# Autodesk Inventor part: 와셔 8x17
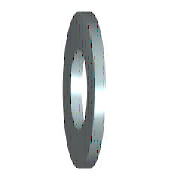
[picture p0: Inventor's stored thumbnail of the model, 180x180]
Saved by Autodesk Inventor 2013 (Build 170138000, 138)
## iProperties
IsCustomPart: 1
Created: 2012-02
Part Number: 와셔 8x17
Material: 강철, 연강
Description: 평면 와셔
Document SubType Name: Modeling
Standard: KS B 1326
Designer: mduedu
Standards Organization: KS
Language: ko-KR
Size Designation: 8x17
Categories: <MemberInstance><Categories><Category DisplayName="조임쇠" InternalName="e4da775c-781d-43d5-af7c-5136215cf5a6" Mnemonic="FSTN"><Category DisplayName="와셔" InternalN
Density: 7.86 g/cm^3
Mass: 2.15757 g
Surface Area: 4.70799 cm^2
Volume: 0.2745 cm^3
Author: mduedu
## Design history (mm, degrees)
sketch "스케치"
  geometry: C1 r 8.5 at (0, 0); C2 r 4.2 at (0, 0); 1 further point
  constraints: 2 centre point, 2 coincident
  dimensions: "d0" = 8.4 diameter of C2 (= SD1); "d1" = 17 diameter of C1 (= SD2)
extrude "본체" new body sketch "스케치" distance "d2" = 1.6 (= SD); taper "d3" = 0 deg
workaxis "Work Axis1"
workplane "Work Plane1"
body "Solid1"
other parameters: "SD1" = 8.4 [user parameter; used in 1 equation term], "SD2" = 17 [user parameter; used in 1 equation term], "SD" = 1.6 [user parameter; used in 1 equation term], "d4" = 0, "d5" = 0, "d6" = 0, "d7" = 0, "NND" = 8 [user parameter]
